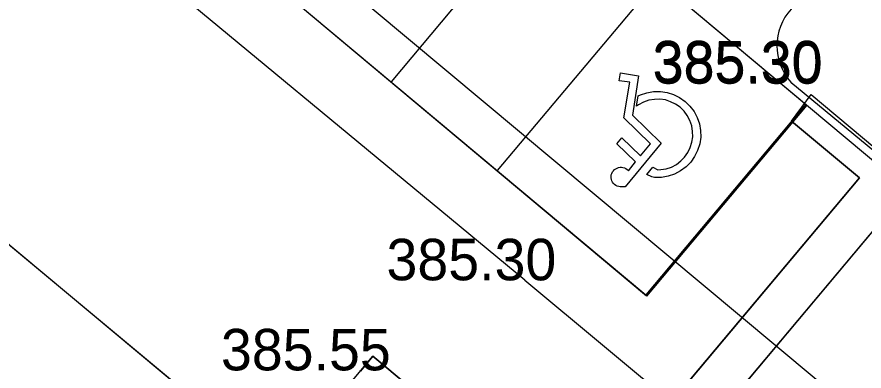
# Model space of a CAD drawing. Extents: x -438233 to -437334, y -1133133 to -1132623.
# Drawn here: x -438115.63 to -438100.33, y -1132983.61 to -1132977.21 of the extents above; entities that cross this region are included whole.
import ezdxf

# ---------------------------------------------------------------- set-up
doc = ezdxf.new("R2010")
doc.units = 0
for name, color, linetype in [('Vrstva 1', 7, 'Continuous'), ('Vrstva 10', 7, 'Continuous'), ('Vrstva 11', 7, 'Continuous'), ('Vrstva 15', 7, 'Continuous'), ('Vrstva 3', 7, 'Continuous'), ('Vrstva 5', 7, 'Continuous'), ('Vrstva 50', 7, 'Continuous'), ('Vrstva 55', 7, 'Continuous')]:
    doc.layers.add(name, color=color, linetype=linetype)

msp = doc.modelspace()

# ---------------------------------------------------------------- linework, layer by layer
at = {"layer": 'Vrstva 1'}
for p, q in [((-438115.61, -1132966.865), (-438098.33, -1132981.342)), ((-438118.649, -1132970.19), (-438104.276, -1132982.231)), ((-438105.985, -1132974.929), (-438108.875, -1132978.378)), ((-438104.069, -1132976.534), (-438106.959, -1132979.983)), ((-438101.653, -1132978.388), (-438101.653, -1132978.388)), ((-438101.646, -1132978.413), (-438101.646, -1132978.413)), ((-438101.386, -1132978.782), (-438104.276, -1132982.231)), ((-438106.458, -1132981.967), (-438106.458, -1132981.967)), ((-438109.448, -1132983.596), (-438109.448, -1132983.596))]:
    msp.add_line(p, q, dxfattribs=at)
for points in [[(-438104.517, -1132978.982), (-438103.997, -1132979.488), (-438104.645, -1132980.279), (-438104.737, -1132980.276), (-438104.762, -1132980.274), (-438104.79, -1132980.265), (-438104.816, -1132980.253), (-438104.839, -1132980.236), (-438104.858, -1132980.217), (-438104.876, -1132980.195), (-438104.886, -1132980.171), (-438104.896, -1132980.143), (-438104.901, -1132980.116), (-438104.901, -1132980.089), (-438104.897, -1132980.061), (-438104.888, -1132980.035), (-438104.876, -1132980.009), (-438104.86, -1132979.987), (-438104.84, -1132979.967), (-438104.818, -1132979.95), (-438104.794, -1132979.938), (-438104.767, -1132979.928), (-438104.74, -1132979.924), (-438104.714, -1132979.924), (-438104.686, -1132979.927), (-438104.658, -1132979.936), (-438104.634, -1132979.947), (-438104.612, -1132979.964), (-438104.593, -1132979.983), (-438104.588, -1132979.987), (-438104.459, -1132979.828), (-438104.796, -1132979.499), (-438104.706, -1132979.389), (-438104.368, -1132979.718), (-438104.188, -1132979.5), (-438104.67, -1132979.031), (-438104.565, -1132978.388), (-438104.755, -1132978.359), (-438104.731, -1132978.219), (-438104.403, -1132978.272), (-438104.517, -1132978.982)], [(-438104.371, -1132978.613), (-438104.253, -1132978.575), (-438104.133, -1132978.554), (-438104.011, -1132978.552), (-438103.89, -1132978.571), (-438103.772, -1132978.606), (-438103.664, -1132978.66), (-438103.563, -1132978.732), (-438103.476, -1132978.816), (-438103.402, -1132978.915), (-438103.345, -1132979.022), (-438103.307, -1132979.139), (-438103.285, -1132979.258), (-438103.283, -1132979.382), (-438103.301, -1132979.502), (-438103.338, -1132979.619), (-438103.392, -1132979.727), (-438103.463, -1132979.829), (-438103.547, -1132979.916), (-438103.648, -1132979.989), (-438103.754, -1132980.047), (-438103.87, -1132980.085), (-438103.989, -1132980.107), (-438104.114, -1132980.109), (-438104.168, -1132980.099), (-438104.257, -1132980.056), (-438104.147, -1132979.922), (-438104.057, -1132979.968), (-438104.005, -1132979.966), (-438103.907, -1132979.95), (-438103.811, -1132979.919), (-438103.721, -1132979.872), (-438103.64, -1132979.809), (-438103.573, -1132979.74), (-438103.513, -1132979.658), (-438103.47, -1132979.568), (-438103.44, -1132979.471), (-438103.427, -1132979.372), (-438103.428, -1132979.274), (-438103.444, -1132979.173), (-438103.477, -1132979.079), (-438103.524, -1132978.99), (-438103.583, -1132978.91), (-438103.655, -1132978.84), (-438103.735, -1132978.784), (-438103.827, -1132978.738), (-438103.921, -1132978.707), (-438104.022, -1132978.695), (-438104.12, -1132978.697), (-438104.22, -1132978.713), (-438104.316, -1132978.745), (-438104.403, -1132978.792), (-438104.442, -1132978.821), (-438104.411, -1132978.635), (-438104.371, -1132978.613)]]:
    msp.add_lwpolyline(points, dxfattribs=at)
at = {"layer": 'Vrstva 10'}
msp.add_lwpolyline([(-438136.916, -1132976.04), (-438130.815, -1132968.777), (-438110.909, -1132985.383), (-438109.206, -1132983.342), (-438101.698, -1132989.616), (-438102.771, -1132990.9), (-438091.189, -1133000.578), (-438097.908, -1133008.583)], close=True, dxfattribs=at)
for points in [[(-438106.458, -1132981.967), (-438114.656, -1132975.171)], [(-438101.653, -1132978.388), (-438085.456, -1132991.774)], [(-438106.458, -1132981.967), (-438090.957, -1132994.89), (-438086.882, -1132998.283), (-438085.153, -1132999.203), (-438079.851, -1133001.541), (-438076.272, -1133002.948)]]:
    msp.add_lwpolyline(points, dxfattribs=at)
msp.add_arc((-438100.918, -1132977.727), 0.988, 53.6213, 221.9841, dxfattribs=at)
at = {"layer": 'Vrstva 11'}
msp.add_lwpolyline([(-438101.698, -1132989.616), (-438109.206, -1132983.342), (-438109.43, -1132983.611)], dxfattribs=at)
at = {"layer": 'Vrstva 15'}
for p, q in [((-438101.643, -1132979.088), (-438100.416, -1132980.116)), ((-438100.416, -1132980.116), (-438105.626, -1132986.334)), ((-438099.803, -1132980.63), (-438105.012, -1132986.847))]:
    msp.add_line(p, q, dxfattribs=at)
msp.add_lwpolyline([(-438101.643, -1132979.088), (-438101.288, -1132978.609), (-438098.247, -1132981.16), (-438098.587, -1132981.649), (-438099.803, -1132980.63), (-438105.012, -1132986.847), (-438105.626, -1132986.334), (-438100.416, -1132980.116)], close=True, dxfattribs=at)
at = {"layer": 'Vrstva 5'}
msp.add_line((-438130.84, -1132968.756), (-438110.909, -1132985.383), dxfattribs=at)
at = {"layer": 'Vrstva 50'}
msp.add_lwpolyline([(-438115.759, -1132966.741), (-438101.366, -1132978.798), (-438104.261, -1132982.253), (-438118.653, -1132970.196)], close=True, dxfattribs=at)
at = {"layer": 'Vrstva 55'}
msp.add_lwpolyline([(-438074.959, -1133013.61), (-438076.856, -1133009.846), (-438083.298, -1132998.719), (-438115.192, -1132972.054), (-438146.469, -1132953.711), (-438176.9, -1132931.48)], dxfattribs=at)

# ---------------------------------------------------------------- texts
at = {"layer": 'Vrstva 3'}
for s, p in [('385.30 ', (-438104.153, -1132978.388)), ('385.30 ', (-438104.146, -1132978.413)), ('385.30 ', (-438108.958, -1132981.967)), ('385.55 ', (-438111.948, -1132983.596))]:
    msp.add_text(s, height=0.75, dxfattribs=at).set_placement(p)

doc.saveas('drawing.dxf')
